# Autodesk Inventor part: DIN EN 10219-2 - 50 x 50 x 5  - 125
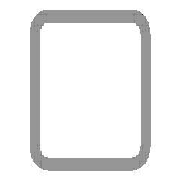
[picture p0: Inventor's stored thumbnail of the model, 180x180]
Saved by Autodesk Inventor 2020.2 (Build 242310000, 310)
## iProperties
_CCFamilyMember: 16
_CCFamilyDisplayName: DIN EN 10219-2 (Quadratisches Hohlprofil - Kaltgeformt) - Kaltgeformte, geschweißte Baustahl-Hohlprofile aus unlegiertem Feinkorn-Baustahl
_FrameMemberDoc: Frame Member File
_Version: 15.0.0
_GetPNFromCC: 1
IsCustomPart: 1
Created: 2019-11
Part Number: DIN EN 10219-2 - 50 x 50 x 5  - 125
Material: Stahl, weich
Description: Kaltgeformte, geschweißte Baustahl-Hohlprofile aus unlegiertem Feinkorn-Baustahl
Document SubType Name: Modeling
Standard: DIN
Designer: lutzd
Standard Revision: 2006-07
Standards Organization: DIN
Language: de-DE
Size Designation: 50 x 50 x 5
Categories: <MemberInstance><Categories><Category DisplayName="Profile" InternalName="089c4875-fa83-4c05-b084-43b9cc11f5ed" Mnemonic="GRDR"><CategoryParameter DisplayName="
Stock Number: 50 x 50 x 5
Mass: 819.952 g
Surface Area: 434.522 cm^2
Volume: 104.452 cm^3
Density: 7.85 g/cm^3
Appearance: Semi-Polished(8)
G_L: 125,000 mm
G_W: 50,000 mm
G_H: 50,000 mm
Mass: 0,82 kg
VLT_Material: Stahl, weich
DocNumber: ADSK-014412
Folder: .
Dimensions: 50x50x125 mm
Title: Profil-Bauteil
Author: lutzd
Revision Number: -
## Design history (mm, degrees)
node "Startebene"
node "Endebene"
sketch "Skizze"
  geometry: L1 (-25, -15)-(-25, 15); L2 (-15, 25)-(15, 25); L3 (25, 15)-(25, -15); L4 (15, -25)-(-15, -25); L5 (-15, 20)-(15, 20); L6 (20, 15)-(20, -15); L7 (15, -20)-(-15, -20); L8 (-20, -15)-(-20, 15); L9 (0, 37.899)-(0, -37.899) reference; L10 (-37.899, 0)-(37.899, 0) reference; A1 r 10 centre (-15, -15) between (-25, -15) and (-15, -25); A2 r 10 centre (-15, 15) between (-15, 25) and (-25, 15); A3 r 10 centre (15, 15) between (25, 15) and (15, 25); A4 r 10 centre (15, -15) between (15, -25) and (25, -15); A5 r 5 centre (-15, 15) between (-15, 20) and (-20, 15); A6 r 5 centre (15, 15) between (20, 15) and (15, 20); A7 r 5 centre (15, -15) between (15, -20) and (20, -15); A8 r 5 centre (-15, -15) between (-20, -15) and (-15, -20)
  constraints: 16 end point, 16 point on circle, 8 centre point, 8 tangent, 4 parallel, 3 equal radius, 2 perpendicular, 7 other
  dimensions: "d7" = 10 radius of A1 (= G_IR); "d10" = 50 distance between parallel lines of L2 L4 (= G_H); "d11" = 50 distance between parallel lines of L1 L3 (= G_W); "d12" = 5 distance between parallel lines of L3 L6 (= G_T); "d15" = 25 distance between parallel lines of L2 L10 (= 0.5 x d10); "d16" = 25 distance between parallel lines of L9 L3 (= 0.5 x d11)
extrude "Körper" new body sketch "Skizze" stored distance "d3" = 125 (= G_L); taper "d4" = 0 deg
node "Driven Length"
  sketch "Sketch3"
    geometry: L1 (0, 0)-(10, 0) reference
    constraints: 2 end point, 1 horizontal
  workplane "Work Plane3"
  sketch "Sketch4"
    geometry: L1 (-2, 0)-(12, 0) reference; L2 (-2, 125)-(12, 125) reference
    dimensions: "d18" = 125 distance between parallel lines of L1 L2 (derived)
body "Solid1"
other parameters: "G_W" = 50 [user parameter; used in 1 equation term], "G_H" = 50 [user parameter; used in 1 equation term], "G_T" = 5 [user parameter; used in 1 equation term], "G_IR" = 10 [user parameter; used in 1 equation term], "G_L" = 125 (= d18) [user parameter; used in 1 equation term], "G_OFFSET_START" = 0 [user parameter; used in 1 equation term], "G_OFFSET_END" = 0 [user parameter; used in 1 equation term], "d13" = 0 (computed from G_OFFSET_START), "d14" = 125 (= G_OFFSET_END + B_L), "B_L" = 125 [user parameter; used in 1 equation term], "d17" = 90 deg
